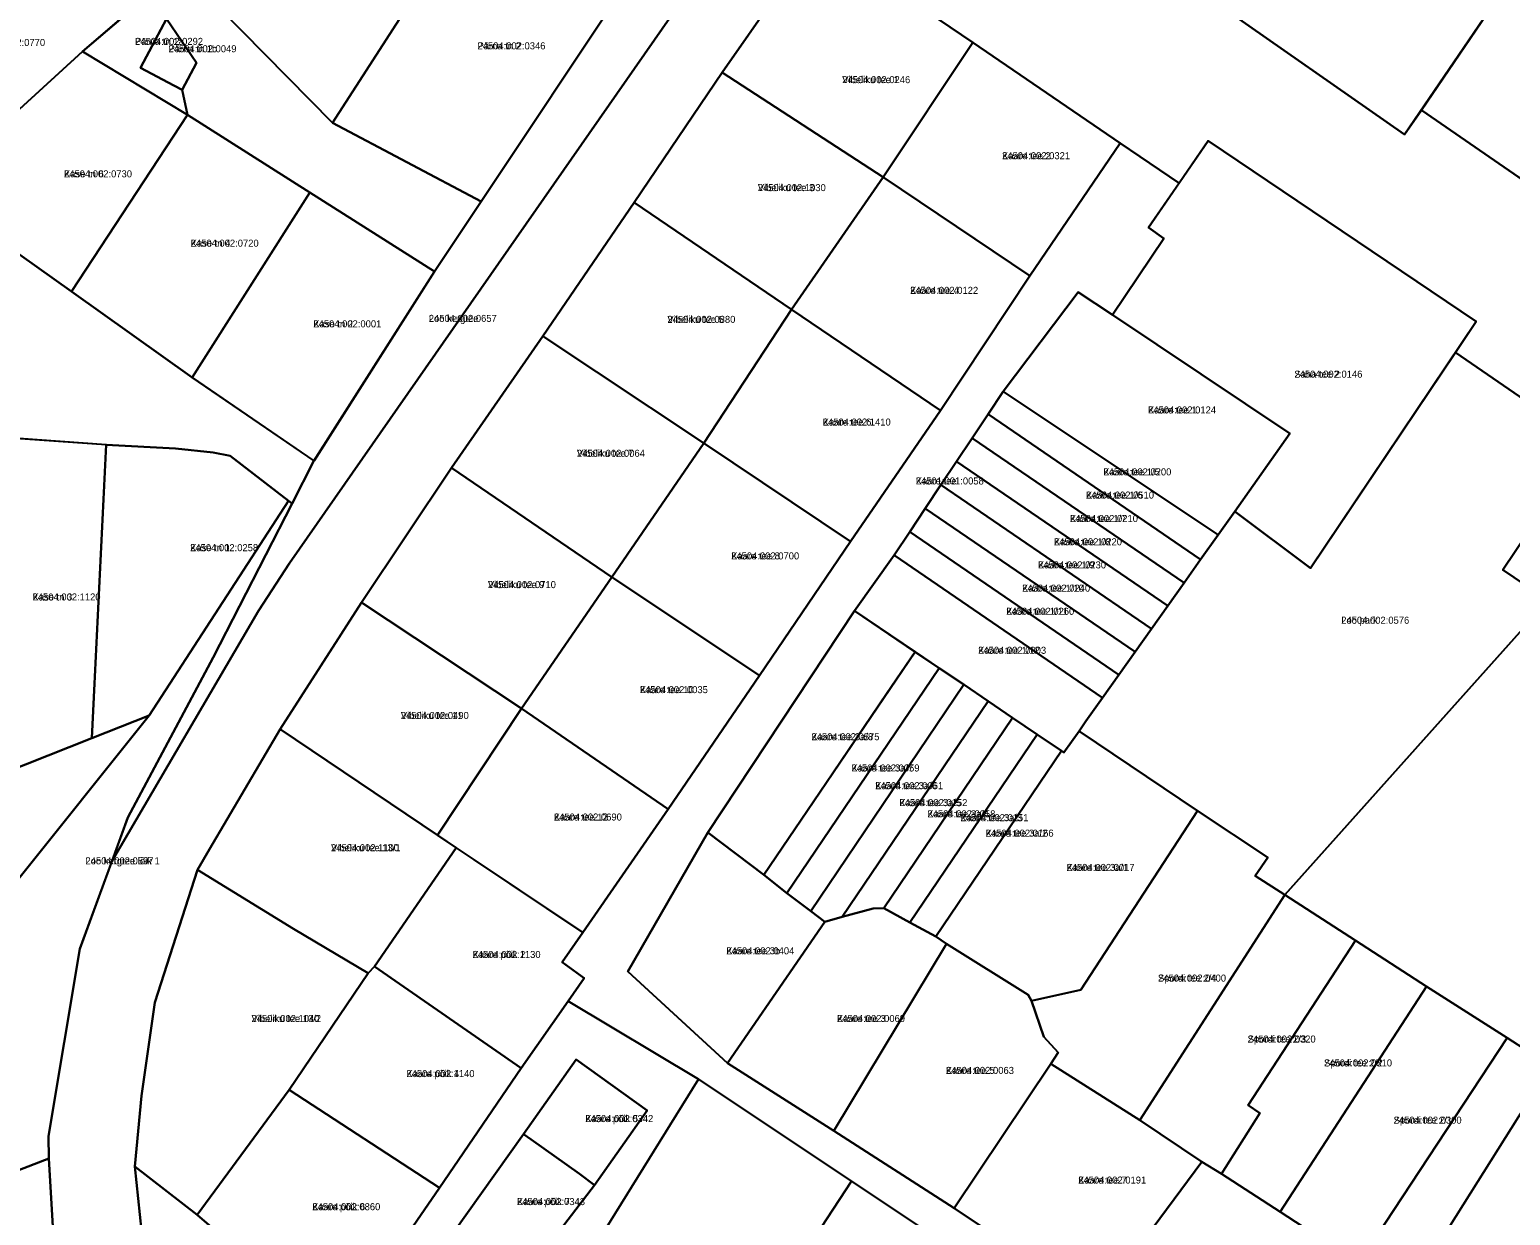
# Model space of a CAD drawing. Extents: x 551291 to 575799, y 6581704 to 6610137.
# Drawn here: x 553257.5 to 553573.3, y 6588762.8 to 6589015.7 of the extents above; entities that cross this region are included whole.
import ezdxf

# ---------------------------------------------------------------- set-up
doc = ezdxf.new("R2010")
doc.units = 0
for name, color, linetype in [('L_AADRESS', 7, 'Continuous'), ('PIIR', 7, 'Continuous'), ('TUNNUS', 7, 'Continuous')]:
    doc.layers.add(name, color=color, linetype=linetype)

msp = doc.modelspace()

# ---------------------------------------------------------------- linework, layer by layer
at = {"layer": 'PIIR'}
for points in [[(553306.96, 6589241.42), (553418.75, 6589107.11), (553465.1, 6589057.77), (553426.41, 6589023.65), (553416.94, 6589023.42), (553405.24, 6589006.54), (553386.47, 6588978.82), (553366.97, 6588950.29), (553347.5, 6588922.26), (553328.32, 6588893.48), (553310.97, 6588866.48), (553295.9, 6588840.93), (553293.3, 6588836.47), (553284.25, 6588808.2), (553281.37, 6588788.28), (553279.94, 6588773.2), (553281.34, 6588759.56), (553286.75, 6588712.18), (553292.54, 6588694.23), (553302.76, 6588674.21), (553322.1, 6588639.57), (553327.9, 6588642.55), (553333.21, 6588633.65)], [(553304.25, 6588635.73), (553276.09, 6588686.81), (553268.73, 6588707.38), (553263.45, 6588743.45), (553261.61, 6588774.94), (553261.53, 6588779.69), (553268.25, 6588819.66), (553275.1, 6588838.43), (553306.34, 6588891.77), (553312.93, 6588901.87), (553404.2, 6589032.89), (553408.34, 6589040.49), (553410.17, 6589044.79), (553406.72, 6589048.87), (553402.28, 6589051.83), (553400.8, 6589049.61), (553398.49, 6589073.95), (553395.53, 6589101.85), (553384.69, 6589115.08), (553365.54, 6589138.04), (553346.66, 6589161.17), (553325.86, 6589186.24), (553304.84, 6589211.6), (553283.11, 6589237.87)], [(552987.46, 6589221.09), (552996.13, 6589179.71), (553015.61, 6589144.56), (553032.97, 6589119.27), (553044.81, 6589101.34), (553061.59, 6589069.5), (553081.67, 6589036.33), (553098.19, 6589009.03), (553115.45, 6588981.63), (553133.28, 6588953.24), (553151.85, 6588924.7), (553154, 6588914.4), (553168.49, 6588890.04), (553200.1, 6588836.89), (553225.39, 6588797.38), (553242.99, 6588767.77), (553261.61, 6588774.94), (553263.45, 6588743.45), (553268.73, 6588707.38), (553276.09, 6588686.81), (553304.25, 6588635.73)], [(553457.1, 6588753.9), (553432.77, 6588770.1), (553400.19, 6588791.84), (553372.38, 6588808.49), (553375.79, 6588813.36), (553371.06, 6588816.82), (553375.51, 6588823.13), (553393.72, 6588849.46), (553413.18, 6588877.93), (553432.54, 6588906.54), (553451.75, 6588934.49), (553470.85, 6588963.2), (553490.06, 6588991.51), (553502.63, 6588982.98), (553496.12, 6588973.48), (553499.4, 6588971.16), (553488.48, 6588954.85), (553481.14, 6588959.72), (553465.15, 6588938.55), (553461.91, 6588933.68), (553458.49, 6588928.55), (553455.17, 6588923.56), (553451.85, 6588918.58), (553448.53, 6588913.58), (553445.21, 6588908.6), (553441.89, 6588903.61), (553433.41, 6588891.71), (553402.18, 6588844.43), (553385.08, 6588814.82), (553406.33, 6588795.27), (553429.02, 6588780.8), (553454.68, 6588764.35), (553485.08, 6588744.02)], [(553248.37, 6588972.62), (553266.48, 6588959.83), (553292.18, 6588941.51), (553318.15, 6588923.71), (553313.47, 6588914.66), (553312.72, 6588915.18), (553300.31, 6588924.76), (553296.64, 6588925.52), (553288.66, 6588926.39), (553273.87, 6588927.17), (553245.3, 6588929.2)], [(553581.34, 6588893.93), (553571.67, 6588900.47), (553589.84, 6588927.45)], [(553324.04, 6588738.25), (553344.91, 6588768.66), (553362.37, 6588794.17), (553372.38, 6588808.49), (553400.19, 6588791.84), (553375.41, 6588751.96)], [(553540.98, 6588752.6), (553572.58, 6588800.64), (553577.24, 6588797.65)], [(553586.81, 6588802.61), (553558.93, 6588758.15)], [(553363.5, 6588750.35), (553377.97, 6588769.25), (553389.18, 6588785.16), (553374.05, 6588796.06), (553362.84, 6588780.12), (553344.93, 6588754.96)], [(553281.34, 6588759.56), (553279.94, 6588773.2), (553293.22, 6588762.88), (553310.27, 6588748.34)]]:
    msp.add_lwpolyline(points, dxfattribs=at)
for points in [[(553200.7, 6589156.06), (553184.93, 6589186.13), (553196.59, 6589192.25), (553210.08, 6589166.68), (553228.39, 6589133.98), (553244.41, 6589102.46), (553261.79, 6589069.3), (553284.6, 6589038.66), (553298.08, 6589020.22), (553322.14, 6588995.79), (553353.8, 6588979.04), (553343.84, 6588964.11), (553317.25, 6588980.99), (553291.21, 6588997.51), (553290.08, 6589002.89), (553293.13, 6589008.65), (553286.68, 6589017.98), (553280.69, 6589021.2), (553266.16, 6589041.06), (553251.75, 6589065.19), (553249.82, 6589064.3), (553234.73, 6589091.25), (553216.01, 6589126.59)], [(553554.33, 6588998.55), (553592.83, 6589055.08), (553642.76, 6589127.92), (553652.25, 6589121.35), (553665.29, 6589139.81), (553677.22, 6589131.17), (553721.16, 6589119.16), (553685.89, 6589061.76), (553650.87, 6589010.32), (553672.84, 6588967.01), (553649.59, 6588932.85)], [(553545.18, 6589090.6), (553592.83, 6589055.08), (553550.71, 6588993.32), (553510, 6589021.75), (553542.75, 6589069.27), (553547.74, 6589076.37), (553539.36, 6589082.27)], [(553329.86, 6589060.3), (553352.89, 6589043.6), (553322.14, 6588995.79), (553298.08, 6589020.22), (553284.6, 6589038.66), (553326.9, 6589065.4)], [(553465.1, 6589057.77), (553510, 6589021.75), (553550.71, 6588993.32), (553554.33, 6588998.55), (553710.92, 6588890.56), (553705.52, 6588882.6), (553702.73, 6588869.78), (553694.94, 6588858.19), (553685.79, 6588864.47), (553641.15, 6588895.18), (553600.81, 6588922.28), (553589.84, 6588927.45), (553561.57, 6588946.83), (553566.01, 6588953.43), (553508.85, 6588991.96), (553502.63, 6588982.98), (553490.06, 6588991.51), (553458.67, 6589012.92), (553441.99, 6589024.36), (553426.41, 6589023.65)], [(553402.28, 6589051.83), (553406.72, 6589048.87), (553410.17, 6589044.79), (553408.34, 6589040.49), (553404.2, 6589032.89), (553312.93, 6588901.87), (553306.34, 6588891.77), (553275.1, 6588838.43), (553278.46, 6588847.64), (553296.63, 6588881.81), (553313.47, 6588914.66), (553318.15, 6588923.71), (553343.84, 6588964.11), (553353.8, 6588979.04), (553383.89, 6589024.22), (553400.8, 6589049.61)], [(553352.89, 6589043.6), (553383.89, 6589024.22), (553353.8, 6588979.04), (553322.14, 6588995.79)], [(553220.32, 6589016.02), (553266.16, 6589041.06), (553280.73, 6589021.2), (553268.8, 6589011.01), (553238.49, 6588983.37)], [(553416.94, 6589023.42), (553426.41, 6589023.65), (553441.99, 6589024.36), (553458.67, 6589012.92), (553439.51, 6588984.2), (553405.24, 6589006.54)], [(553268.8, 6589011.01), (553280.69, 6589021.2), (553286.68, 6589017.98), (553284.26, 6589013.44), (553281.13, 6589007.58), (553288.26, 6589003.81), (553290.08, 6589002.89), (553291.21, 6588997.51)], [(553293.13, 6589008.65), (553290.08, 6589002.89), (553288.26, 6589003.81), (553281.13, 6589007.58), (553284.26, 6589013.44), (553286.68, 6589017.98)], [(553458.67, 6589012.92), (553490.06, 6588991.51), (553470.85, 6588963.2), (553439.51, 6588984.2)], [(553241.84, 6588978.93), (553238.49, 6588983.37), (553268.8, 6589011.01), (553291.21, 6588997.51), (553266.48, 6588959.83), (553248.37, 6588972.62)], [(553405.24, 6589006.54), (553439.51, 6588984.2), (553419.97, 6588955.97), (553386.47, 6588978.82)], [(553317.25, 6588980.99), (553292.18, 6588941.51), (553266.48, 6588959.83), (553291.21, 6588997.51)], [(553508.85, 6588991.96), (553566.01, 6588953.43), (553530.64, 6588900.85), (553514.51, 6588912.89), (553526.27, 6588929.53), (553488.48, 6588954.85), (553499.4, 6588971.16), (553496.12, 6588973.48)], [(553451.75, 6588934.49), (553419.97, 6588955.97), (553439.51, 6588984.2), (553470.85, 6588963.2)], [(553343.85, 6588964.09), (553318.22, 6588923.75), (553292.18, 6588941.51), (553317.25, 6588980.99)], [(553366.97, 6588950.29), (553386.47, 6588978.82), (553419.97, 6588955.97), (553401.3, 6588927.47)], [(553488.48, 6588954.85), (553526.27, 6588929.53), (553514.51, 6588912.89), (553510.96, 6588907.94), (553465.15, 6588938.55), (553481.14, 6588959.72)], [(553419.97, 6588955.97), (553451.75, 6588934.49), (553432.54, 6588906.54), (553401.3, 6588927.47)], [(553401.3, 6588927.47), (553381.71, 6588898.9), (553347.5, 6588922.26), (553366.97, 6588950.29)], [(553561.57, 6588946.83), (553589.84, 6588927.45), (553571.67, 6588900.47), (553581.34, 6588893.93), (553525.19, 6588831.13), (553518.87, 6588835.24), (553521.56, 6588839.1), (553506.55, 6588849.1), (553481.37, 6588866.05), (553482.77, 6588868.19), (553486.35, 6588873.18), (553489.82, 6588878.08), (553493.29, 6588882.98), (553496.76, 6588887.88), (553500.23, 6588892.78), (553503.7, 6588897.68), (553507.25, 6588902.7), (553510.96, 6588907.94), (553514.51, 6588912.89), (553530.64, 6588900.85)], [(553510.96, 6588907.94), (553507.25, 6588902.7), (553461.91, 6588933.68), (553465.15, 6588938.55)], [(553461.91, 6588933.68), (553507.25, 6588902.7), (553503.7, 6588897.68), (553458.49, 6588928.55)], [(553245.3, 6588929.2), (553273.85, 6588927.21), (553270.78, 6588864.58), (553242.44, 6588853.36)], [(553273.87, 6588927.17), (553288.66, 6588926.39), (553296.64, 6588925.52), (553300.31, 6588924.76), (553312.72, 6588915.18), (553283.01, 6588869.39), (553270.78, 6588864.58)], [(553432.54, 6588906.54), (553413.18, 6588877.93), (553381.71, 6588898.9), (553401.3, 6588927.47)], [(553503.7, 6588897.68), (553500.23, 6588892.78), (553455.17, 6588923.56), (553458.49, 6588928.55)], [(553455.17, 6588923.56), (553500.23, 6588892.78), (553496.76, 6588887.88), (553451.85, 6588918.58)], [(553347.5, 6588922.26), (553381.71, 6588898.9), (553362.44, 6588870.9), (553328.32, 6588893.48)], [(553451.85, 6588918.58), (553496.76, 6588887.88), (553493.29, 6588882.98), (553448.53, 6588913.58)], [(553312.72, 6588915.18), (553313.47, 6588914.66), (553296.63, 6588881.81), (553278.46, 6588847.64), (553268.25, 6588819.66), (553261.53, 6588779.69), (553261.61, 6588774.94), (553242.99, 6588767.77), (553225.39, 6588797.38), (553283.01, 6588869.39)], [(553448.53, 6588913.58), (553493.29, 6588882.98), (553489.82, 6588878.08), (553445.21, 6588908.6)], [(553445.21, 6588908.6), (553489.82, 6588878.08), (553486.35, 6588873.18), (553441.89, 6588903.61)], [(553482.77, 6588868.19), (553481.37, 6588866.05), (553478.1, 6588861.53), (553477.56, 6588861.89), (553472.38, 6588865.39), (553467.14, 6588868.94), (553461.93, 6588872.46), (553456.72, 6588875.99), (553451.51, 6588879.5), (553446.31, 6588883.02), (553433.41, 6588891.71), (553441.89, 6588903.61), (553486.35, 6588873.18)], [(553393.72, 6588849.46), (553362.44, 6588870.9), (553381.71, 6588898.9), (553413.18, 6588877.93)], [(553362.44, 6588870.9), (553344.52, 6588843.86), (553310.97, 6588866.48), (553328.32, 6588893.48)], [(553622.65, 6588865.98), (553577.24, 6588797.65), (553572.58, 6588800.64), (553555.41, 6588811.64), (553540.24, 6588821.43), (553525.19, 6588831.13), (553581.34, 6588893.93)], [(553433.41, 6588891.71), (553446.33, 6588883), (553440.26, 6588874.04), (553427.28, 6588854.89), (553414.08, 6588835.42), (553402.18, 6588844.43)], [(553414.08, 6588835.42), (553446.33, 6588883), (553451.51, 6588879.5), (553418.97, 6588831.53)], [(553418.97, 6588831.53), (553451.51, 6588879.5), (553456.72, 6588875.99), (553424.08, 6588827.66)], [(553456.72, 6588875.99), (553461.93, 6588872.46), (553430.82, 6588826.45), (553427.09, 6588825.43), (553424.08, 6588827.66)], [(553362.44, 6588870.9), (553393.72, 6588849.46), (553375.51, 6588823.13), (553344.52, 6588843.86)], [(553461.93, 6588872.46), (553467.14, 6588868.94), (553439.66, 6588828.31), (553437.4, 6588828.24), (553430.82, 6588826.45)], [(553283.01, 6588869.39), (553225.39, 6588797.38), (553200.1, 6588836.89), (553213.04, 6588841.86), (553242.44, 6588853.36), (553270.78, 6588864.58)], [(553439.66, 6588828.31), (553467.14, 6588868.94), (553472.38, 6588865.39), (553445.22, 6588825.29)], [(553344.52, 6588843.86), (553348.48, 6588841.22), (553331.05, 6588815.91), (553329.72, 6588814.44), (553313.8, 6588823.92), (553293.3, 6588836.47), (553295.9, 6588840.93), (553310.97, 6588866.48)], [(553445.22, 6588825.29), (553472.38, 6588865.39), (553477.56, 6588861.89), (553450.77, 6588822.28)], [(553477.56, 6588861.89), (553478.1, 6588861.53), (553481.37, 6588866.05), (553506.55, 6588849.1), (553481.72, 6588810.9), (553471.14, 6588808.56), (553470.43, 6588809.87), (553453.08, 6588820.72), (553450.77, 6588822.28)], [(553475.29, 6588795.15), (553476.83, 6588797.55), (553473.82, 6588800.88), (553471.14, 6588808.56), (553481.72, 6588810.9), (553506.55, 6588849.1), (553521.56, 6588839.1), (553518.87, 6588835.24), (553525.19, 6588831.13), (553494.29, 6588783.09)], [(553402.18, 6588844.43), (553414.08, 6588835.42), (553418.97, 6588831.53), (553424.08, 6588827.66), (553427.09, 6588825.43), (553406.33, 6588795.27), (553385.08, 6588814.82)], [(553375.51, 6588823.13), (553371.06, 6588816.82), (553375.79, 6588813.36), (553372.38, 6588808.49), (553362.37, 6588794.17), (553331.05, 6588815.91), (553348.48, 6588841.22)], [(553279.94, 6588773.2), (553281.37, 6588788.28), (553284.25, 6588808.2), (553293.3, 6588836.47), (553313.8, 6588823.92), (553329.72, 6588814.44), (553312.85, 6588789.54), (553293.22, 6588762.88)], [(553494.29, 6588783.09), (553525.19, 6588831.13), (553540.24, 6588821.43), (553517.37, 6588786.28), (553519.84, 6588784.61), (553511.71, 6588771.65), (553507.53, 6588774.2)], [(553429.02, 6588780.8), (553406.33, 6588795.27), (553427.09, 6588825.43), (553430.82, 6588826.45), (553437.4, 6588828.24), (553439.66, 6588828.31), (553445.22, 6588825.29), (553450.77, 6588822.28), (553453.08, 6588820.72)], [(553471.14, 6588808.56), (553473.82, 6588800.88), (553476.83, 6588797.55), (553475.29, 6588795.15), (553454.68, 6588764.35), (553429.02, 6588780.8), (553453.08, 6588820.72), (553470.43, 6588809.87)], [(553511.71, 6588771.65), (553519.84, 6588784.61), (553517.37, 6588786.28), (553540.24, 6588821.43), (553555.41, 6588811.64), (553524.22, 6588763.56)], [(553331.05, 6588815.91), (553362.37, 6588794.17), (553344.91, 6588768.66), (553312.85, 6588789.54), (553329.72, 6588814.44)], [(553572.58, 6588800.64), (553540.98, 6588752.6), (553524.22, 6588763.56), (553555.41, 6588811.64)], [(553586.81, 6588802.61), (553623.3, 6588779.03), (553593.12, 6588735.52), (553558.93, 6588758.15)], [(553374.05, 6588796.06), (553389.18, 6588785.16), (553377.97, 6588769.25), (553374.81, 6588771.64), (553364.44, 6588778.96), (553362.84, 6588780.12)], [(553485.08, 6588744.02), (553454.68, 6588764.35), (553475.29, 6588795.15), (553494.29, 6588783.09), (553507.53, 6588774.2)], [(553432.77, 6588770.1), (553406.91, 6588730.55), (553375.41, 6588751.96), (553400.19, 6588791.84)], [(553344.91, 6588768.66), (553324.04, 6588738.25), (553310.27, 6588748.34), (553293.22, 6588762.88), (553312.85, 6588789.54)], [(553362.84, 6588780.12), (553364.44, 6588778.96), (553374.81, 6588771.64), (553377.97, 6588769.25), (553363.5, 6588750.35), (553360.96, 6588752.16), (553355.97, 6588755.7), (553351.65, 6588750.19), (553346.52, 6588753.84), (553344.93, 6588754.96)], [(553507.53, 6588774.2), (553511.71, 6588771.65), (553524.22, 6588763.56), (553540.98, 6588752.6), (553544.73, 6588750.38), (553527.99, 6588725.41), (553521.94, 6588719.68), (553485.08, 6588744.02)], [(553406.91, 6588730.55), (553432.77, 6588770.1), (553457.1, 6588753.9), (553430.53, 6588714.52)]]:
    msp.add_lwpolyline(points, close=True, dxfattribs=at)

# ---------------------------------------------------------------- texts
at = {"layer": 'L_AADRESS'}
for s, p in [('Pärna tn 1a', (553280, 6589012.44)), ('Pärna tn 1b', (553287.13, 6589010.87)), ('Pärna tn 2', (553353.02, 6589011.49)), ('Vibeliku tee 1', (553430.81, 6589004.28)), ('Kaare tee 2', (553464.9, 6588988.06)), ('Kase tn 6', (553264.85, 6588984.19)), ('Vibeliku tee 3', (553412.8, 6588981.25)), ('Kase tn 4', (553291.86, 6588969.41)), ('Kaare tee 4', (553445.3, 6588959.34)), ('Loo kergtee', (553342.64, 6588953.36)), ('Kase tn 2', (553318.02, 6588952.2)), ('Vibeliku tee 5', (553393.52, 6588953.15)), ('Saha tee 2', (553527.24, 6588941.47)), ('Kaare tee 1', (553496.03, 6588933.83)), ('Kaare tee 6', (553426.65, 6588931.25)), ('Vibeliku tee 7', (553374.23, 6588924.59)), ('Kaare tee', (553446.5, 6588918.69)), ('Kaare tee 1/5', (553486.5, 6588920.62)), ('Kaare tee 1/6', (553482.8, 6588915.68)), ('Kaare tee 1/7', (553479.37, 6588910.67)), ('Kase tn 1', (553291.75, 6588904.46)), ('Kaare tee 1/8', (553475.97, 6588905.72)), ('Kaare tee 8', (553407.13, 6588902.7)), ('Kaare tee 1/9', (553472.57, 6588900.78)), ('Vibeliku tee 9', (553355.25, 6588896.58)), ('Kase tn 3', (553258.14, 6588893.94)), ('Kaare tee 1/10', (553469.18, 6588895.83)), ('Kaare tee 1/11', (553465.79, 6588890.89)), ('Loo park', (553537.23, 6588888.98)), ('Kaare tee 1/12', (553459.8, 6588882.57)), ('Kaare tee 10', (553387.66, 6588874.18)), ('Vibeliku tee 11', (553336.67, 6588868.67)), ('Kaare tee 3a/8', (553424.25, 6588864.14)), ('Kaare tee 3a/7', (553432.79, 6588857.47)), ('Kaare tee 3a/6', (553437.84, 6588853.7)), ('Kaare tee 3a/5', (553443, 6588850.08)), ('Kaare tee 12', (553369.32, 6588847.01)), ('Kaare tee 3a/4', (553448.98, 6588847.7)), ('Kaare tee 3a/3', (553456.02, 6588846.87)), ('Kaare tee 3a/2', (553461.39, 6588843.57)), ('Vibeliku tee 13/1', (553321.79, 6588840.46)), ('Loo kergtee lõik 1', (553269.43, 6588837.66)), ('Kaare tee 3a/1', (553478.66, 6588836.26)), ('Kaare põik 2', (553351.98, 6588817.7)), ('Kaare tee 3b', (553406.09, 6588818.48)), ('Spordi tee 2/4', (553498.16, 6588812.66)), ('Vibeliku tee 13/2', (553304.83, 6588804.03)), ('Kaare tee 3', (553429.7, 6588804.04)), ('Spordi tee 2/3', (553517.27, 6588799.66)), ('Kaare põik 4', (553337.89, 6588792.29)), ('Kaare tee 5', (553452.93, 6588792.97)), ('Spordi tee 2/2', (553533.56, 6588794.56)), ('Kaare põik 5', (553376.01, 6588782.69)), ('Spordi tee 2/1', (553548.4, 6588782.36)), ('Kaare tee 7', (553481.14, 6588769.58)), ('Kaare põik 6', (553317.8, 6588763.9)), ('Kaare põik 7', (553361.45, 6588764.99))]:
    msp.add_text(s, height=1.5, dxfattribs=at).set_placement(p)
at = {"layer": 'TUNNUS'}
for s, p in [('24504:002:0770', (553246.32, 6589012.21)), ('24504:002:0292', (553280, 6589012.44)), ('24504:002:0049', (553287.13, 6589010.87)), ('24504:002:0346', (553353.02, 6589011.49)), ('24504:002:0246', (553430.81, 6589004.28)), ('24504:002:0321', (553464.9, 6588988.06)), ('24504:002:0730', (553264.85, 6588984.19)), ('24504:002:1030', (553412.8, 6588981.25)), ('24504:002:0720', (553291.86, 6588969.41)), ('24504:002:0122', (553445.3, 6588959.34)), ('24504:002:0001', (553318.02, 6588952.2)), ('24504:002:0657', (553342.64, 6588953.36)), ('24504:002:0880', (553393.52, 6588953.15)), ('24504:002:0146', (553527.24, 6588941.47)), ('24504:002:0124', (553496.03, 6588933.83)), ('24504:002:1410', (553426.65, 6588931.25)), ('24504:002:0064', (553374.23, 6588924.59)), ('24501:001:0058', (553446.5, 6588918.69)), ('24504:002:0200', (553486.5, 6588920.62)), ('24504:002:0510', (553482.8, 6588915.68)), ('24504:002:0210', (553479.37, 6588910.67)), ('24504:002:0258', (553291.75, 6588904.46)), ('24504:002:0220', (553475.97, 6588905.72)), ('24504:002:0700', (553407.13, 6588902.7)), ('24504:002:0230', (553472.57, 6588900.78)), ('24504:002:0710', (553355.25, 6588896.58)), ('24504:002:1120', (553258.14, 6588893.94)), ('24504:002:0240', (553469.18, 6588895.83)), ('24504:002:0260', (553465.79, 6588890.89)), ('24504:002:0576', (553537.23, 6588888.98)), ('24504:002:0003', (553459.8, 6588882.57)), ('24504:002:0035', (553387.66, 6588874.18)), ('24504:002:0490', (553336.67, 6588868.67)), ('24504:002:0575', (553424.25, 6588864.14)), ('24504:002:0059', (553432.79, 6588857.47)), ('24504:002:0061', (553437.84, 6588853.7)), ('24504:002:0152', (553443, 6588850.08)), ('24504:002:0690', (553369.32, 6588847.01)), ('24504:002:0058', (553448.98, 6588847.7)), ('24504:002:0151', (553456.02, 6588846.87)), ('24504:002:0166', (553461.39, 6588843.57)), ('24504:002:1100', (553321.79, 6588840.46)), ('24504:002:0597', (553269.43, 6588837.66)), ('24504:002:0017', (553478.66, 6588836.26)), ('24504:002:1130', (553351.98, 6588817.7)), ('24504:002:0404', (553406.09, 6588818.48)), ('24504:002:0400', (553498.16, 6588812.66)), ('24504:002:1040', (553304.83, 6588804.03)), ('24504:002:0069', (553429.7, 6588804.04)), ('24504:002:0320', (553517.27, 6588799.66)), ('24504:002:0063', (553452.93, 6588792.97)), ('24504:002:0310', (553533.56, 6588794.56)), ('24504:002:1140', (553337.89, 6588792.29)), ('24504:002:0342', (553376.01, 6588782.69)), ('24504:002:0300', (553548.4, 6588782.36)), ('24504:002:0191', (553481.14, 6588769.58)), ('24504:002:0343', (553361.45, 6588764.99)), ('24504:002:0860', (553317.8, 6588763.9))]:
    msp.add_text(s, height=1.5, dxfattribs=at).set_placement(p)

doc.saveas('drawing.dxf')
